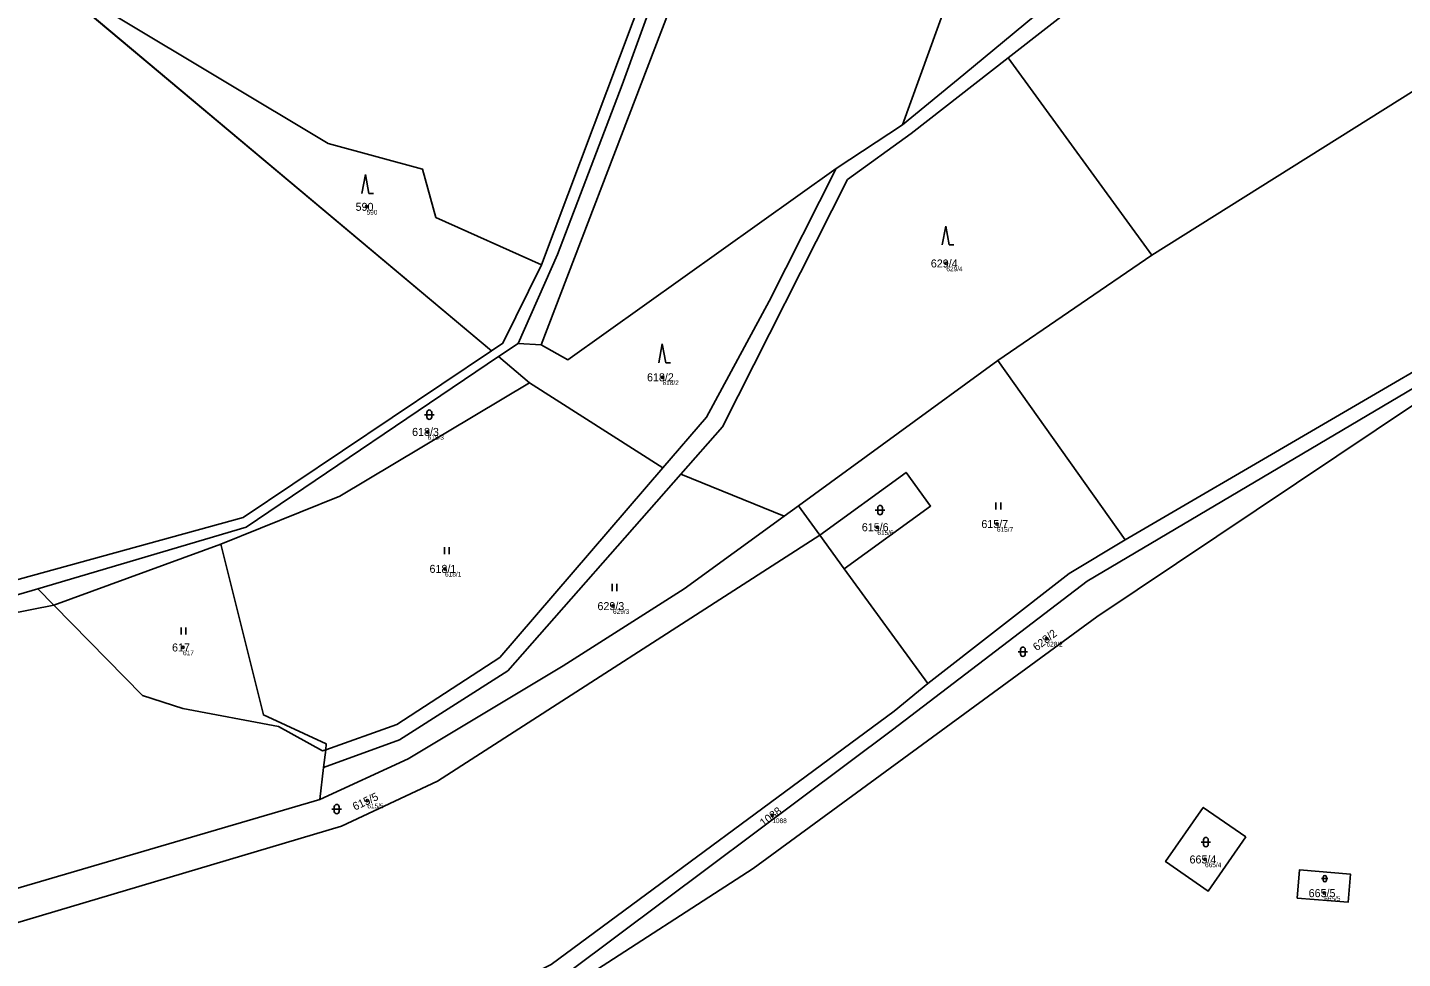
# Model space of a CAD drawing. Extents: x -554500 to -548272, y -1079733 to -1073730.
# Drawn here: x -552836.2 to -552544.1, y -1076175.5 to -1075977.7 of the extents above; entities that cross this region are included whole.
import ezdxf

# ---------------------------------------------------------------- set-up
doc = ezdxf.new("R2010")
doc.units = 0
for name, color, linetype in [('Definiční body', 7, 'Continuous'), ('Hranice parcel', 7, 'Continuous'), ('Parcelní čísla', 7, 'Continuous'), ('Polygon parcely', 7, 'Continuous'), ('Značky kultur', 7, 'Continuous')]:
    doc.layers.add(name, color=color, linetype=linetype)

msp = doc.modelspace()

# ---------------------------------------------------------------- linework, layer by layer
at = {"layer": 'Definiční body'}
for centre in [(-552764.13, -1076015.76994), (-552640.96, -1076027.80994), (-552701.25, -1076051.98994), (-552751.16, -1076063.59994), (-552655.62, -1076083.84994), (-552630.22, -1076083.16994), (-552747.46, -1076092.69994), (-552711.78, -1076100.60994), (-552619.68, -1076107.53994), (-552803.13, -1076109.39994), (-552763.97, -1076141.91994), (-552677.93, -1076145.06994), (-552586, -1076154.43994), (-552560.69, -1076161.59994)]:
    msp.add_circle(centre, 0.25, dxfattribs=at)
at = {"layer": 'Hranice parcel'}
for p, q in [((-552828.94, -1075969.72), (-552737.59, -1076046.37)), ((-552597.31, -1076026.03), (-552627.82, -1075984.12)), ((-552664.37, -1076007.63), (-552650.3, -1075998.38)), ((-552597.31, -1076026.03), (-552629.99, -1076048.43)), ((-552731.95, -1076044.8), (-552736.11, -1076047.61)), ((-552731.95, -1076044.8), (-552727.04, -1076045.08)), ((-552736.11, -1076047.61), (-552729.52, -1076053.14)), ((-552629.99, -1076048.43), (-552672.38, -1076079.28)), ((-552603, -1076086.54), (-552629.99, -1076048.43)), ((-552701.18, -1076071.23), (-552729.52, -1076053.14)), ((-552675.41, -1076081.49), (-552697.34, -1076072.56)), ((-552672.38, -1076079.28), (-552675.41, -1076081.49)), ((-552667.84, -1076085.54), (-552672.38, -1076079.28)), ((-552662.64, -1076092.68), (-552667.84, -1076085.54)), ((-552795.11, -1076087.45), (-552830.56, -1076100.44)), ((-552644.88, -1076117.08), (-552662.64, -1076092.68)), ((-552833.99, -1076096.95), (-552830.56, -1076100.44)), ((-552773.26, -1076134.88), (-552772.82, -1076131.12)), ((-552774.05, -1076141.73), (-552773.26, -1076134.88))]:
    msp.add_line(p, q, dxfattribs=at)
for points in [[(-552726.95, -1076028.08), (-552704.81, -1075969.12), (-552685.78, -1075917.84), (-552682.79, -1075913.09), (-552662.88, -1075890.4), (-552650.62, -1075889.09)], [(-552644.8, -1075891.54), (-552661.5, -1075892.75), (-552681.92, -1075916.73), (-552691.6, -1075939.65), (-552709.83, -1075989.85), (-552723.58, -1076025.93), (-552731.95, -1076044.8)], [(-552644.8, -1075891.54), (-552659.51, -1075896.88), (-552678.74, -1075918.98), (-552727.04, -1076045.08)], [(-552619.1, -1075914.64), (-552646.1, -1075936.71), (-552633.8, -1075952.74), (-552650.3, -1075998.38)], [(-552650.3, -1075998.38), (-552637.22, -1075987.66), (-552605.17, -1075961.05), (-552563.28, -1075942.71), (-552519.79, -1075921.15)], [(-552627.82, -1075984.12), (-552601.93, -1075963.89), (-552593.13, -1075960.12)], [(-552819.08, -1075965.85), (-552817.55, -1075975.21), (-552772.3, -1076002.3), (-552752.23, -1076007.78), (-552749.41, -1076018.04), (-552726.95, -1076028.08)], [(-552504.51, -1075977.4), (-552537.93, -1075988.82), (-552597.31, -1076026.03)], [(-552627.82, -1075984.12), (-552648.46, -1076000.22), (-552661.96, -1076009.97), (-552688.49, -1076062.51), (-552697.34, -1076072.56)], [(-552727.04, -1076045.08), (-552721.34, -1076048.25), (-552664.37, -1076007.63)], [(-552701.18, -1076071.23), (-552691.89, -1076060.44), (-552678.59, -1076035.79), (-552664.37, -1076007.63)], [(-552719.9, -1076180.87), (-552681.98, -1076156.35), (-552608.99, -1076102.89), (-552524.19, -1076046.12), (-552491.18, -1076033.46), (-552463.07, -1076021.08), (-552440.38, -1076010.58)], [(-552737.59, -1076046.37), (-552735.18, -1076044.75), (-552726.95, -1076028.08)], [(-552491.34, -1076027.29), (-552490.6, -1076029.85), (-552524.54, -1076044.1), (-552611.08, -1076095.31), (-552652.41, -1076126.93), (-552720.77, -1076178.05), (-552734.53, -1076185.13)], [(-552603, -1076086.54), (-552523.8, -1076040.38), (-552491.34, -1076027.29)], [(-552860.14, -1076096.43), (-552840.02, -1076095.45), (-552790.38, -1076081.78), (-552737.59, -1076046.37)], [(-552736.11, -1076047.61), (-552789.7, -1076083.85), (-552833.99, -1076096.95)], [(-552729.52, -1076053.14), (-552769.81, -1076077.24), (-552795.11, -1076087.45)], [(-552772.82, -1076131.12), (-552757.73, -1076125.75), (-552735.85, -1076111.54), (-552701.18, -1076071.23)], [(-552662.64, -1076092.68), (-552644.3, -1076079.34), (-552649.5, -1076072.19), (-552667.84, -1076085.54)], [(-552697.34, -1076072.56), (-552734.1, -1076114.34), (-552757.13, -1076129.04), (-552773.26, -1076134.88)], [(-552675.41, -1076081.49), (-552696.65, -1076096.97), (-552722.39, -1076113.31), (-552755.26, -1076133.09), (-552774.05, -1076141.73)], [(-552667.84, -1076085.54), (-552749.05, -1076137.84), (-552769.43, -1076147.39), (-552924.37, -1076193.48), (-552926.61, -1076186.44), (-552774.05, -1076141.73)], [(-552644.88, -1076117.08), (-552614.84, -1076093.69), (-552603, -1076086.54)], [(-552912.15, -1076088.67), (-552896.99, -1076092.77), (-552860.62, -1076099.7), (-552838.1, -1076098.16), (-552833.99, -1076096.95)], [(-552772.82, -1076131.12), (-552772.68, -1076129.88), (-552786.03, -1076123.72), (-552795.11, -1076087.45)], [(-552830.56, -1076100.44), (-552854.71, -1076105.19), (-552917.93, -1076121.8)], [(-552772.82, -1076131.12), (-552773.47, -1076131.35), (-552782.83, -1076126.18), (-552803.17, -1076122.39), (-552811.71, -1076119.63), (-552830.56, -1076100.44)], [(-552899.32, -1076232.57), (-552890.99, -1076229.04), (-552857.28, -1076221.66), (-552738.28, -1076183.37), (-552724.95, -1076176.74), (-552652.03, -1076122.91), (-552644.88, -1076117.08)], [(-552577.34, -1076149.66), (-552585.33, -1076161.16), (-552594.37, -1076154.88), (-552586.38, -1076143.38), (-552577.34, -1076149.66)], [(-552566.44, -1076162.64), (-552565.94, -1076156.66), (-552555.13, -1076157.55), (-552555.62, -1076163.53), (-552566.44, -1076162.64)]]:
    msp.add_lwpolyline(points, dxfattribs=at)
at = {"layer": 'Polygon parcely'}
for points in [[(-552749.41, -1076018.04), (-552726.95, -1076028.08), (-552704.81, -1075969.12), (-552685.78, -1075917.84), (-552682.79, -1075913.09), (-552662.88, -1075890.4), (-552650.62, -1075889.09), (-552655.38, -1075855.14), (-552719.15, -1075896.31), (-552737.28, -1075914.96), (-552814.25, -1075963.45), (-552819.08, -1075965.85), (-552817.55, -1075975.21), (-552772.3, -1076002.3), (-552752.23, -1076007.78)], [(-552605.17, -1075961.05), (-552563.28, -1075942.71), (-552519.79, -1075921.15), (-552499.71, -1075908.68), (-552462.98, -1075893.87), (-552492.77, -1075883.63), (-552531.08, -1075877.51), (-552579.48, -1075895.39), (-552608.55, -1075897.13), (-552611.68, -1075908.58), (-552619.1, -1075914.64), (-552646.1, -1075936.71), (-552633.8, -1075952.74), (-552650.3, -1075998.38), (-552637.22, -1075987.66)], [(-552644.8, -1075891.54), (-552659.51, -1075896.88), (-552678.74, -1075918.98), (-552727.04, -1076045.08), (-552721.34, -1076048.25), (-552664.37, -1076007.63), (-552650.3, -1075998.38), (-552633.8, -1075952.74), (-552646.1, -1075936.71), (-552619.1, -1075914.64), (-552619.53, -1075888.47), (-552626.67, -1075890.77)], [(-552709.83, -1075989.85), (-552723.58, -1076025.93), (-552731.95, -1076044.8), (-552727.04, -1076045.08), (-552678.74, -1075918.98), (-552659.51, -1075896.88), (-552644.8, -1075891.54), (-552661.5, -1075892.75), (-552681.92, -1075916.73), (-552691.6, -1075939.65)], [(-552537.93, -1075988.82), (-552597.31, -1076026.03), (-552629.99, -1076048.43), (-552603, -1076086.54), (-552523.8, -1076040.38), (-552491.34, -1076027.29), (-552440.41, -1076004.43), (-552440.24, -1075953.59), (-552504.51, -1075977.4)], [(-552735.18, -1076044.75), (-552726.95, -1076028.08), (-552749.41, -1076018.04), (-552752.23, -1076007.78), (-552772.3, -1076002.3), (-552817.55, -1075975.21), (-552819.08, -1075965.85), (-552828.94, -1075969.72), (-552737.59, -1076046.37)], [(-552995.96, -1076056.98), (-552930.41, -1076069.82), (-552860.14, -1076096.43), (-552840.02, -1076095.45), (-552790.38, -1076081.78), (-552737.59, -1076046.37), (-552828.94, -1075969.72), (-552838.34, -1075973.42), (-552861.56, -1075982.55), (-552851.15, -1075985.37), (-552900.4, -1076003.39)], [(-552661.96, -1076009.97), (-552688.49, -1076062.51), (-552697.34, -1076072.56), (-552675.41, -1076081.49), (-552672.38, -1076079.28), (-552629.99, -1076048.43), (-552597.31, -1076026.03), (-552627.82, -1075984.12), (-552648.46, -1076000.22)], [(-552463.07, -1076021.08), (-552440.38, -1076010.58), (-552440.41, -1076004.43), (-552491.34, -1076027.29), (-552490.6, -1076029.85), (-552524.54, -1076044.1), (-552611.08, -1076095.31), (-552652.41, -1076126.93), (-552720.77, -1076178.05), (-552734.53, -1076185.13), (-552719.9, -1076180.87), (-552681.98, -1076156.35), (-552608.99, -1076102.89), (-552524.19, -1076046.12), (-552491.18, -1076033.46)], [(-552736.11, -1076047.61), (-552729.52, -1076053.14), (-552701.18, -1076071.23), (-552691.89, -1076060.44), (-552678.59, -1076035.79), (-552664.37, -1076007.63), (-552721.34, -1076048.25), (-552727.04, -1076045.08), (-552731.95, -1076044.8)], [(-552440.38, -1076010.58), (-552463.07, -1076021.08), (-552491.18, -1076033.46), (-552524.19, -1076046.12), (-552608.99, -1076102.89), (-552681.98, -1076156.35), (-552719.9, -1076180.87), (-552732.29, -1076192.03), (-552885.51, -1076239.42), (-552920.5, -1076268.01), (-552896.74, -1076279.5), (-552872.63, -1076284.51), (-552836.56, -1076293.49), (-552778.78, -1076319.71), (-552727.41, -1076304.16), (-552661.17, -1076268), (-552652.28, -1076251.74), (-552600.15, -1076234.56), (-552558.11, -1076199.44), (-552532.71, -1076183.86), (-552533.07, -1076183.41), (-552475.95, -1076098.51), (-552430.36, -1076052.94)], [(-552833.99, -1076096.95), (-552830.56, -1076100.44), (-552795.11, -1076087.45), (-552769.81, -1076077.24), (-552729.52, -1076053.14), (-552736.11, -1076047.61), (-552789.7, -1076083.85)], [(-552614.84, -1076093.69), (-552603, -1076086.54), (-552629.99, -1076048.43), (-552672.38, -1076079.28), (-552667.84, -1076085.54), (-552649.5, -1076072.19), (-552644.3, -1076079.34), (-552662.64, -1076092.68), (-552644.88, -1076117.08)], [(-552735.85, -1076111.54), (-552701.18, -1076071.23), (-552729.52, -1076053.14), (-552769.81, -1076077.24), (-552795.11, -1076087.45), (-552786.03, -1076123.72), (-552772.68, -1076129.88), (-552772.82, -1076131.12), (-552757.73, -1076125.75)], [(-552649.5, -1076072.19), (-552667.84, -1076085.54), (-552662.64, -1076092.68), (-552644.3, -1076079.34)], [(-552773.26, -1076134.88), (-552774.05, -1076141.73), (-552755.26, -1076133.09), (-552722.39, -1076113.31), (-552696.65, -1076096.97), (-552675.41, -1076081.49), (-552697.34, -1076072.56), (-552734.1, -1076114.34), (-552757.13, -1076129.04)], [(-552755.26, -1076133.09), (-552774.05, -1076141.73), (-552926.61, -1076186.44), (-552924.37, -1076193.48), (-552769.43, -1076147.39), (-552749.05, -1076137.84), (-552667.84, -1076085.54), (-552672.38, -1076079.28), (-552675.41, -1076081.49), (-552696.65, -1076096.97), (-552722.39, -1076113.31)], [(-552917.93, -1076121.8), (-552854.71, -1076105.19), (-552830.56, -1076100.44), (-552833.99, -1076096.95), (-552838.1, -1076098.16), (-552860.62, -1076099.7), (-552896.99, -1076092.77), (-552912.15, -1076088.67), (-552947.08, -1076086.65), (-552950.9, -1076092.26), (-553010.93, -1076086.68), (-552999.87, -1076099.51), (-552943.33, -1076118.81)], [(-552795.11, -1076087.45), (-552830.56, -1076100.44), (-552811.71, -1076119.63), (-552803.17, -1076122.39), (-552782.83, -1076126.18), (-552773.47, -1076131.35), (-552772.82, -1076131.12), (-552772.68, -1076129.88), (-552786.03, -1076123.72)], [(-552577.34, -1076149.66), (-552586.38, -1076143.38), (-552594.37, -1076154.88), (-552585.33, -1076161.16)], [(-552577.34, -1076149.66), (-552585.33, -1076161.16), (-552594.37, -1076154.88), (-552586.38, -1076143.38)], [(-552566.44, -1076162.64), (-552555.62, -1076163.53), (-552555.13, -1076157.55), (-552565.94, -1076156.66)], [(-552566.44, -1076162.64), (-552565.94, -1076156.66), (-552555.13, -1076157.55), (-552555.62, -1076163.53)]]:
    msp.add_lwpolyline(points, close=True, dxfattribs=at)
for points in [[(-553084, -1076120.53), (-553035.75, -1076085.34), (-553012.89, -1076076.96), (-552954.39, -1076079.91), (-552942.21, -1076080.53), (-552912.15, -1076088.67), (-552896.99, -1076092.77), (-552860.62, -1076099.7), (-552838.1, -1076098.16), (-552833.99, -1076096.95), (-552789.7, -1076083.85), (-552736.11, -1076047.61), (-552731.95, -1076044.8), (-552723.58, -1076025.93), (-552709.83, -1075989.85), (-552691.6, -1075939.65)], [(-552605.17, -1075961.05), (-552637.22, -1075987.66), (-552650.3, -1075998.38), (-552664.37, -1076007.63), (-552678.59, -1076035.79), (-552691.89, -1076060.44), (-552701.18, -1076071.23), (-552735.85, -1076111.54), (-552757.73, -1076125.75), (-552772.82, -1076131.12), (-552773.26, -1076134.88), (-552757.13, -1076129.04), (-552734.1, -1076114.34), (-552697.34, -1076072.56), (-552688.49, -1076062.51), (-552661.96, -1076009.97), (-552648.46, -1076000.22), (-552627.82, -1075984.12), (-552601.93, -1075963.89)], [(-552601.93, -1075963.89), (-552627.82, -1075984.12), (-552597.31, -1076026.03), (-552537.93, -1075988.82), (-552504.51, -1075977.4)], [(-552704.81, -1075969.12), (-552726.95, -1076028.08), (-552735.18, -1076044.75), (-552737.59, -1076046.37), (-552790.38, -1076081.78), (-552840.02, -1076095.45), (-552860.14, -1076096.43), (-552904.6, -1076087.24), (-552940.15, -1076078), (-553014.48, -1076074.23), (-553037.47, -1076082.91), (-553038.93, -1076081.06), (-553086.61, -1076118.06)], [(-552523.8, -1076040.38), (-552603, -1076086.54), (-552614.84, -1076093.69), (-552644.88, -1076117.08), (-552652.03, -1076122.91), (-552724.95, -1076176.74), (-552738.28, -1076183.37), (-552857.28, -1076221.66), (-552890.99, -1076229.04), (-552899.32, -1076232.57), (-552914.51, -1076239), (-552918.75, -1076243), (-552934.05, -1076257.45), (-552947.32, -1076266.26), (-552941.6, -1076266.5), (-552929.44, -1076257.78), (-552913.42, -1076242.21), (-552890.76, -1076232.14), (-552860.92, -1076225.82), (-552734.53, -1076185.13), (-552720.77, -1076178.05), (-552652.41, -1076126.93), (-552611.08, -1076095.31), (-552524.54, -1076044.1)], [(-552724.95, -1076176.74), (-552652.03, -1076122.91), (-552644.88, -1076117.08), (-552662.64, -1076092.68), (-552667.84, -1076085.54), (-552749.05, -1076137.84), (-552769.43, -1076147.39), (-552924.37, -1076193.48)], [(-552926.61, -1076186.44), (-552774.05, -1076141.73), (-552773.26, -1076134.88), (-552772.82, -1076131.12), (-552773.47, -1076131.35), (-552782.83, -1076126.18), (-552803.17, -1076122.39), (-552811.71, -1076119.63), (-552830.56, -1076100.44), (-552854.71, -1076105.19), (-552917.93, -1076121.8), (-552936.23, -1076132.22), (-552940.56, -1076135.41), (-552946.87, -1076140.07), (-552972.64, -1076151.06), (-553010.78, -1076190.42)]]:
    msp.add_lwpolyline(points, dxfattribs=at)
at = {"layer": 'Značky kultur'}
for p, q in [((-552764.39, -1076008.92), (-552765.14, -1076012.92)), ((-552763.64, -1076012.92), (-552764.39, -1076008.92)), ((-552763.64, -1076012.92), (-552762.644, -1076012.92)), ((-552641.09, -1076019.86), (-552641.84, -1076023.86)), ((-552640.34, -1076023.86), (-552641.09, -1076019.86)), ((-552640.34, -1076023.86), (-552639.344, -1076023.86)), ((-552701.3, -1076044.91), (-552702.05, -1076048.91)), ((-552700.55, -1076048.91), (-552701.3, -1076044.91)), ((-552700.55, -1076048.91), (-552699.554, -1076048.91)), ((-552751.801, -1076059.941), (-552749.799, -1076059.941)), ((-552751.301, -1076059.441), (-552751.301, -1076060.442)), ((-552750.299, -1076060.442), (-552750.299, -1076059.441)), ((-552656.051, -1076080.201), (-552654.049, -1076080.201)), ((-552655.551, -1076079.701), (-552655.551, -1076080.702)), ((-552654.549, -1076080.702), (-552654.549, -1076079.701)), ((-552630.421, -1076080.08), (-552630.421, -1076078.58)), ((-552629.42, -1076080.08), (-552629.42, -1076078.58)), ((-552747.561, -1076089.56), (-552747.561, -1076088.06)), ((-552746.56, -1076089.56), (-552746.56, -1076088.06)), ((-552711.991, -1076097.41), (-552711.991, -1076095.91)), ((-552710.99, -1076097.41), (-552710.99, -1076095.91)), ((-552803.531, -1076106.65), (-552803.531, -1076105.15)), ((-552802.53, -1076106.65), (-552802.53, -1076105.15)), ((-552625.701, -1076110.301), (-552623.699, -1076110.301)), ((-552625.201, -1076109.801), (-552625.201, -1076110.802)), ((-552624.199, -1076110.802), (-552624.199, -1076109.801)), ((-552771.481, -1076143.741), (-552769.479, -1076143.741)), ((-552770.981, -1076143.241), (-552770.981, -1076144.242)), ((-552769.979, -1076144.242), (-552769.979, -1076143.241)), ((-552586.821, -1076150.761), (-552584.819, -1076150.761)), ((-552586.321, -1076150.261), (-552586.321, -1076151.262)), ((-552585.319, -1076151.262), (-552585.319, -1076150.261)), ((-552561.231, -1076158.521), (-552559.889, -1076158.521)), ((-552560.895, -1076158.185), (-552560.895, -1076158.856)), ((-552560.225, -1076158.856), (-552560.225, -1076158.185))]:
    msp.add_line(p, q, dxfattribs=at)
for centre, radius, start, end in [((-552750.8, -1076059.4409), 0.5, 0, 180), ((-552750.8, -1076060.4409), 0.5, 180, 359.9878861), ((-552655.05, -1076079.7009), 0.5, 0, 180), ((-552655.05, -1076080.7009), 0.5, 180, 359.9878861), ((-552624.7, -1076109.8009), 0.5, 0, 180), ((-552624.7, -1076110.8009), 0.5, 180, 359.9878861), ((-552770.48, -1076143.2409), 0.5, 0, 180), ((-552770.48, -1076144.2409), 0.5, 180, 359.9878861), ((-552585.82, -1076150.2609), 0.5, 0, 180), ((-552585.82, -1076151.2609), 0.5, 180, 359.9878861), ((-552560.56, -1076158.1856), 0.335, 0, 180), ((-552560.56, -1076158.8556), 0.335, 180, 359.9878861)]:
    msp.add_arc(centre, radius, start, end, dxfattribs=at)

# ---------------------------------------------------------------- texts
at = {"layer": 'Definiční body'}
for s, p in [('590', (-552764.13, -1076017.426)), ('629/4', (-552640.96, -1076029.466)), ('618/2', (-552701.25, -1076053.646)), ('618/3', (-552751.16, -1076065.256)), ('615/7', (-552630.22, -1076084.826)), ('615/6', (-552655.62, -1076085.506)), ('618/1', (-552747.46, -1076094.356)), ('629/3', (-552711.78, -1076102.266)), ('617', (-552803.13, -1076111.056)), ('628/2', (-552619.68, -1076109.196)), ('615/5', (-552763.97, -1076143.576)), ('1088', (-552677.93, -1076146.726)), ('665/4', (-552586, -1076156.096)), ('665/5', (-552560.69, -1076163.256))]:
    msp.add_text(s, height=0.999996, dxfattribs=at).set_placement(p)
at = {"layer": 'Parcelní čísla'}
for s, p in [('590', (-552766.455, -1076016.62)), ('629/4', (-552644.258, -1076028.66)), ('618/2', (-552704.548, -1076052.84)), ('618/3', (-552754.458, -1076064.45)), ('615/6', (-552658.918, -1076084.7)), ('615/7', (-552633.518, -1076084.02)), ('618/1', (-552750.758, -1076093.55)), ('629/3', (-552715.078, -1076101.46)), ('617', (-552805.455, -1076110.25)), ('665/4', (-552589.298, -1076155.29)), ('665/5', (-552563.988, -1076162.45))]:
    msp.add_text(s, height=1.699998, dxfattribs=at).set_placement(p)
for s, rotation, p in [('628/2', 38, (-552621.755, -1076110.24)), ('615/5', 25, (-552766.6, -1076144.084)), ('1088', 37, (-552679.793, -1076147.538))]:
    msp.add_text(s, height=1.699998, rotation=rotation, dxfattribs=at).set_placement(p)

doc.saveas('drawing.dxf')
